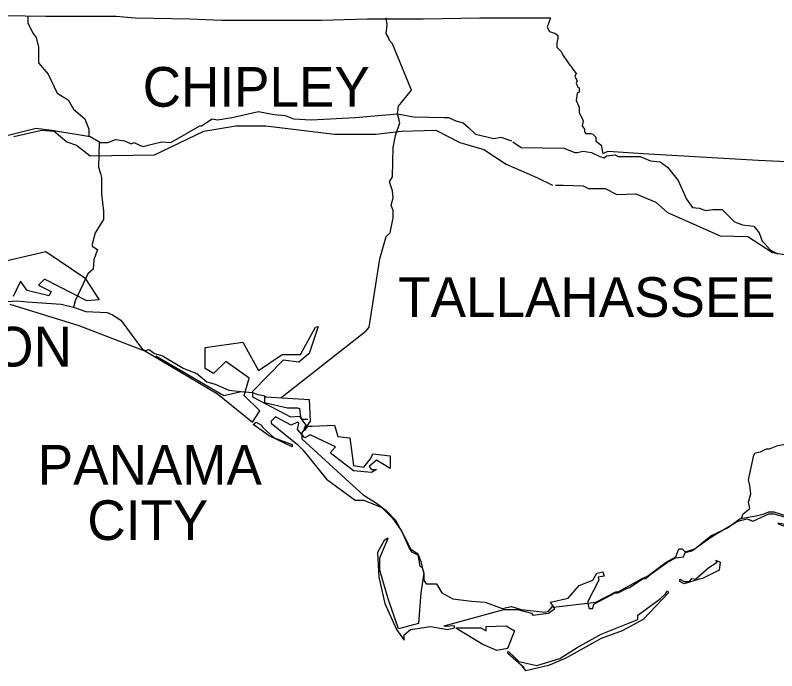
# Model space of a CAD drawing. Extents: x -820.2 to -798.1, y -2199.1 to -2182.2.
# Drawn here: x -807.968 to -807.105, y -2183.81 to -2183.067 of the extents above; entities that cross this region are included whole.
import ezdxf

# ---------------------------------------------------------------- set-up
doc = ezdxf.new("R2010")
doc.units = 0
for name, color, linetype in [('FLMap2', 7, 'Continuous'), ('FLMap3', 7, 'Continuous'), ('TextMisc', 7, 'Continuous')]:
    doc.layers.add(name, color=color, linetype=linetype)

msp = doc.modelspace()

# ---------------------------------------------------------------- linework, layer by layer
at = {"layer": 'FLMap2'}
for points in [[(-807.95384, -2183.06771), (-807.95384, -2183.07565), (-807.94789, -2183.08756), (-807.94441, -2183.09202), (-807.94193, -2183.10294), (-807.94193, -2183.1208), (-807.93102, -2183.1337), (-807.9206, -2183.15503), (-807.9082, -2183.16247), (-807.90224, -2183.17339), (-807.88934, -2183.1843), (-807.88488, -2183.19571), (-807.88488, -2183.20415)], [(-807.66708, -2183.50033), (-807.57033, -2183.42443), (-807.56686, -2183.42046), (-807.55495, -2183.34306), (-807.54751, -2183.31776), (-807.54305, -2183.3133), (-807.53957, -2183.29643), (-807.53957, -2183.28799), (-807.54206, -2183.28204), (-807.53957, -2183.27361), (-807.54057, -2183.26567), (-807.54404, -2183.25574), (-807.54057, -2183.24979), (-807.53957, -2183.21655), (-807.53709, -2183.20316), (-807.53213, -2183.18877), (-807.53461, -2183.17835), (-807.53362, -2183.16992), (-807.51874, -2183.15156), (-807.54057, -2183.09897), (-807.54404, -2183.0955), (-807.54553, -2183.09103), (-807.54751, -2183.08756), (-807.54652, -2183.07764), (-807.54751, -2183.0697)], [(-807.97765, -2183.20316), (-807.94441, -2183.19472), (-807.92655, -2183.1972), (-807.88339, -2183.20415), (-807.87148, -2183.21109), (-807.86305, -2183.21109), (-807.85461, -2183.20762), (-807.8442, -2183.20911), (-807.83675, -2183.21258), (-807.83328, -2183.21109), (-807.82733, -2183.21407), (-807.82286, -2183.21556), (-807.8174, -2183.21407), (-807.81145, -2183.21258), (-807.80202, -2183.2101), (-807.79161, -2183.21109), (-807.75886, -2183.19224), (-807.75688, -2183.19224), (-807.74497, -2183.1843), (-807.73902, -2183.1853), (-807.72215, -2183.18281), (-807.70429, -2183.17835), (-807.69238, -2183.17587), (-807.67452, -2183.17934), (-807.66212, -2183.18033), (-807.65269, -2183.1843), (-807.63285, -2183.1853), (-807.58274, -2183.18281), (-807.53461, -2183.17835), (-807.51675, -2183.18182), (-807.48202, -2183.18281), (-807.47706, -2183.18281), (-807.46863, -2183.18629), (-807.46019, -2183.18877), (-807.45474, -2183.19373), (-807.4463, -2183.20167), (-807.42547, -2183.20663), (-807.41753, -2183.20514), (-807.40562, -2183.20911)], [(-807.87297, -2183.21109), (-807.87396, -2183.23888), (-807.87148, -2183.24632), (-807.87049, -2183.25078), (-807.87049, -2183.26914), (-807.86801, -2183.28899), (-807.86801, -2183.29841), (-807.87744, -2183.3133), (-807.88091, -2183.32619), (-807.88091, -2183.32868), (-807.87495, -2183.33215), (-807.87892, -2183.34405), (-807.87992, -2183.35447), (-807.88587, -2183.35993), (-807.90026, -2183.39069), (-807.90224, -2183.39764)], [(-807.40413, -2183.2101), (-807.39471, -2183.21655), (-807.34609, -2183.21754), (-807.33368, -2183.2225), (-807.3312, -2183.2225), (-807.32426, -2183.22102), (-807.31483, -2183.2225), (-807.3054, -2183.22697), (-807.30044, -2183.22846), (-807.29796, -2183.22598), (-807.28804, -2183.22499), (-807.28457, -2183.22697), (-807.27266, -2183.22697), (-807.25976, -2183.22697), (-807.24785, -2183.23193), (-807.23694, -2183.23292), (-807.2285, -2183.23888), (-807.2166, -2183.25426), (-807.20717, -2183.27509), (-807.20023, -2183.28452), (-807.19278, -2183.28551), (-807.18534, -2183.28799), (-807.1774, -2183.287), (-807.16649, -2183.287), (-807.1526, -2183.30089), (-807.14367, -2183.30437), (-807.13077, -2183.30585), (-807.12481, -2183.3133), (-807.12134, -2183.32272), (-807.11787, -2183.32619), (-807.11192, -2183.33314), (-807.10348, -2183.33711)], [(-808.0104, -2183.35249), (-807.9335, -2183.33463), (-807.88934, -2183.3644), (-807.87297, -2183.3892), (-807.88686, -2183.39069), (-807.93499, -2183.36588), (-807.94193, -2183.37283), (-807.92754, -2183.37978), (-807.93002, -2183.38474), (-807.95483, -2183.37878), (-807.96227, -2183.36837), (-807.97071, -2183.38573)], [(-807.98261, -2183.39168), (-807.96624, -2183.39069), (-807.95483, -2183.39168), (-807.91613, -2183.39416), (-807.90224, -2183.39764), (-807.88835, -2183.4026), (-807.86404, -2183.40359), (-807.85809, -2183.40657), (-807.84866, -2183.41252), (-807.82385, -2183.44576), (-807.82038, -2183.44675), (-807.81641, -2183.44576), (-807.81046, -2183.45023), (-807.80103, -2183.45271), (-807.79954, -2183.45419), (-807.77722, -2183.46709), (-807.76233, -2183.47305), (-807.75092, -2183.48247), (-807.7415, -2183.48495), (-807.72612, -2183.4919), (-807.71223, -2183.49339), (-807.69933, -2183.49438), (-807.69337, -2183.49686), (-807.68643, -2183.49785), (-807.68395, -2183.49934), (-807.63483, -2183.50232), (-807.63384, -2183.52712), (-807.64326, -2183.54002), (-807.64326, -2183.54697), (-807.58968, -2183.59609)], [(-807.97418, -2183.39416), (-807.89629, -2183.41847)], [(-807.89629, -2183.41847), (-807.82038, -2183.44774), (-807.73902, -2183.49587), (-807.69933, -2183.52812), (-807.69089, -2183.51522), (-807.70875, -2183.49785), (-807.7028, -2183.47801), (-807.72959, -2183.45916), (-807.74348, -2183.47305), (-807.75291, -2183.46709), (-807.75291, -2183.44328), (-807.71024, -2183.43733), (-807.69238, -2183.46957), (-807.66559, -2183.45122), (-807.64475, -2183.45122), (-807.62788, -2183.42046), (-807.62491, -2183.41947), (-807.63483, -2183.45023), (-807.64674, -2183.46015), (-807.6646, -2183.45767), (-807.69933, -2183.49339), (-807.69933, -2183.49934), (-807.65616, -2183.52216)], [(-807.80897, -2183.45271), (-807.73157, -2183.49785), (-807.71223, -2183.49339)], [(-807.68544, -2183.49934), (-807.68544, -2183.50579), (-807.65964, -2183.51175), (-807.64823, -2183.51175), (-807.64575, -2183.51274), (-807.64475, -2183.52216), (-807.64326, -2183.52464), (-807.63632, -2183.52464)], [(-807.60606, -2183.53159), (-807.60258, -2183.54449), (-807.58869, -2183.54598), (-807.58472, -2183.57723), (-807.57281, -2183.57922), (-807.56537, -2183.56979), (-807.56289, -2183.56384), (-807.54305, -2183.56632), (-807.54305, -2183.58071), (-807.55843, -2183.57128), (-807.56686, -2183.57823), (-807.56438, -2183.5817), (-807.55843, -2183.5817), (-807.56438, -2183.58517), (-807.58472, -2183.58319), (-807.61102, -2183.56285), (-807.60506, -2183.5559), (-807.63384, -2183.5425), (-807.63979, -2183.54598), (-807.64823, -2183.53655), (-807.64674, -2183.52911), (-807.64823, -2183.52812), (-807.65517, -2183.53159), (-807.67303, -2183.52216), (-807.67799, -2183.52712), (-807.67799, -2183.52911), (-807.64823, -2183.55342), (-807.64227, -2183.55937), (-807.61548, -2183.59261), (-807.58274, -2183.61643), (-807.57281, -2183.61643), (-807.55247, -2183.62486), (-807.54057, -2183.63677)], [(-807.65616, -2183.52216), (-807.64575, -2183.52117), (-807.64227, -2183.52712), (-807.6388, -2183.53159), (-807.64078, -2183.53506), (-807.64078, -2183.53655), (-807.63979, -2183.53754), (-807.63632, -2183.53258), (-807.63136, -2183.53258)], [(-807.69833, -2183.5306), (-807.69486, -2183.52812), (-807.68891, -2183.53159), (-807.68742, -2183.53407)], [(-807.68742, -2183.53407), (-807.67452, -2183.54598), (-807.65418, -2183.55342), (-807.65418, -2183.5559), (-807.65418, -2183.5559), (-807.68047, -2183.5435), (-807.69833, -2183.5306)], [(-807.63136, -2183.53258), (-807.60606, -2183.53159)], [(-807.14466, -2183.63677), (-807.14268, -2183.63181), (-807.13523, -2183.62585), (-807.13672, -2183.61891), (-807.13424, -2183.60948), (-807.13523, -2183.60006), (-807.13672, -2183.59361), (-807.13077, -2183.56533), (-807.12928, -2183.56285), (-807.12333, -2183.56185), (-807.11638, -2183.55838), (-807.11291, -2183.55838), (-807.10348, -2183.55441), (-807.09703, -2183.55342), (-807.09356, -2183.55441), (-807.08512, -2183.55094)], [(-807.58968, -2183.59609), (-807.57381, -2183.61047), (-807.55843, -2183.6199), (-807.54751, -2183.62833), (-807.53709, -2183.63925), (-807.52469, -2183.66207), (-807.52023, -2183.6715), (-807.51179, -2183.67745), (-807.50832, -2183.68588), (-807.50485, -2183.70027), (-807.50485, -2183.70722), (-807.50237, -2183.71119), (-807.49046, -2183.71119), (-807.4845, -2183.72161), (-807.4721, -2183.72855), (-807.45077, -2183.73103), (-807.43539, -2183.73202), (-807.41604, -2183.73947), (-807.40562, -2183.73699), (-807.39471, -2183.74046), (-807.36742, -2183.74344), (-807.36345, -2183.74244), (-807.35899, -2183.73699), (-807.35799, -2183.73798), (-807.30987, -2183.73202), (-807.30987, -2183.73202), (-807.28705, -2183.72061), (-807.28457, -2183.72061), (-807.25728, -2183.70523), (-807.25133, -2183.70275), (-807.22999, -2183.68688), (-807.21908, -2183.68092), (-807.21561, -2183.6715), (-807.21213, -2183.6715), (-807.20866, -2183.67497), (-807.19774, -2183.6715), (-807.17939, -2183.65711), (-807.16054, -2183.64768), (-807.14664, -2183.63776), (-807.14367, -2183.63677), (-807.12829, -2183.63429), (-807.11886, -2183.63181), (-807.1139, -2183.62982), (-807.10795, -2183.62982), (-807.09356, -2183.63429)], [(-807.13871, -2183.63776), (-807.13176, -2183.64024), (-807.13176, -2183.64024), (-807.1139, -2183.63181), (-807.10795, -2183.63181), (-807.07818, -2183.64024), (-807.07669, -2183.63925), (-807.07123, -2183.6457), (-807.0757, -2183.64768), (-807.10348, -2183.64272), (-807.10249, -2183.64371), (-807.07917, -2183.65116)], [(-807.54057, -2183.63677), (-807.53015, -2183.65116), (-807.52122, -2183.6715), (-807.51874, -2183.67497), (-807.51179, -2183.67844), (-807.50931, -2183.69134), (-807.50683, -2183.69283), (-807.50485, -2183.69928), (-807.50832, -2183.72161), (-807.5108, -2183.75633), (-807.53362, -2183.76229), (-807.54553, -2183.72855), (-807.55495, -2183.69581), (-807.55495, -2183.68192), (-807.54553, -2183.65959), (-807.54999, -2183.66207), (-807.55744, -2183.67596), (-807.55595, -2183.70375), (-807.549, -2183.73351), (-807.5361, -2183.76328), (-807.52717, -2183.77519), (-807.52717, -2183.77072), (-807.52717, -2183.76923), (-807.52023, -2183.76328), (-807.4974, -2183.75981), (-807.47806, -2183.76328), (-807.47012, -2183.7613), (-807.47012, -2183.75882), (-807.48054, -2183.75981), (-807.48202, -2183.75882), (-807.41406, -2183.74046), (-807.39868, -2183.74046), (-807.3828, -2183.74443), (-807.38131, -2183.74691), (-807.36345, -2183.74443), (-807.3565, -2183.73947), (-807.36147, -2183.73202), (-807.34112, -2183.72756), (-807.32872, -2183.71317), (-807.31334, -2183.70722), (-807.30888, -2183.69928), (-807.30193, -2183.69779), (-807.30044, -2183.70275), (-807.30739, -2183.70375), (-807.3064, -2183.70722), (-807.3193, -2183.73202), (-807.31731, -2183.73947), (-807.31334, -2183.73947), (-807.31235, -2183.7345), (-807.28804, -2183.72161)], [(-807.18088, -2183.65959), (-807.17393, -2183.65513), (-807.1526, -2183.64272), (-807.14863, -2183.64024), (-807.13871, -2183.63776), (-807.13424, -2183.63925)], [(-807.28804, -2183.72161), (-807.28457, -2183.72161), (-807.27514, -2183.71664), (-807.27167, -2183.71565), (-807.25629, -2183.70523), (-807.25281, -2183.70523), (-807.24587, -2183.69928), (-807.2285, -2183.68688), (-807.21908, -2183.68192), (-807.21064, -2183.68092), (-807.20866, -2183.67596), (-807.20122, -2183.67398), (-807.18088, -2183.65959)], [(-807.21461, -2183.70871), (-807.21461, -2183.70623), (-807.20965, -2183.70871), (-807.2037, -2183.70871), (-807.20122, -2183.70523), (-807.19675, -2183.70623), (-807.18187, -2183.69283), (-807.17244, -2183.68688), (-807.17393, -2183.6844), (-807.16897, -2183.68688), (-807.16996, -2183.69581)], [(-807.16996, -2183.69581), (-807.18881, -2183.70523), (-807.19278, -2183.70623), (-807.20965, -2183.71119), (-807.21461, -2183.70871)], [(-807.39123, -2183.80644), (-807.41009, -2183.79007), (-807.40909, -2183.78809), (-807.40215, -2183.79454), (-807.39719, -2183.7995), (-807.37685, -2183.80396), (-807.35055, -2183.79602), (-807.3312, -2183.78362), (-807.30392, -2183.76824), (-807.26224, -2183.75187), (-807.26224, -2183.74691), (-807.23694, -2183.72855), (-807.23099, -2183.7226), (-807.2285, -2183.71913), (-807.22751, -2183.72161), (-807.25629, -2183.75187), (-807.2801, -2183.76477), (-807.30392, -2183.7732), (-807.3446, -2183.79602), (-807.36345, -2183.80396), (-807.38925, -2183.80992), (-807.39371, -2183.80396)], [(-807.46863, -2183.7613), (-807.44035, -2183.7613), (-807.4344, -2183.76477), (-807.4344, -2183.75981), (-807.41157, -2183.75882), (-807.40215, -2183.76477), (-807.41009, -2183.78461), (-807.42199, -2183.78709), (-807.43787, -2183.78015), (-807.46764, -2183.76229)], [(-807.46764, -2183.76229), (-807.46863, -2183.7613)]]:
    msp.add_lwpolyline(points, dxfattribs=at)
at = {"layer": 'FLMap3'}
for points in [[(-808.00395, -2183.06672), (-807.9335, -2183.06771), (-807.85362, -2183.06771), (-807.83229, -2183.0697), (-807.77027, -2183.07069), (-807.73406, -2183.07218), (-807.68544, -2183.07218), (-807.62144, -2183.07218), (-807.56885, -2183.07069), (-807.50584, -2183.07069), (-807.44134, -2183.0697), (-807.36147, -2183.0697), (-807.36494, -2183.08012), (-807.36246, -2183.08508), (-807.35551, -2183.08756), (-807.35303, -2183.08954), (-807.35303, -2183.09302), (-807.35402, -2183.09798), (-807.35402, -2183.10294), (-807.34956, -2183.1074), (-807.34708, -2183.11236), (-807.34261, -2183.11832), (-807.34112, -2183.1208), (-807.33219, -2183.13271), (-807.33368, -2183.13618), (-807.3312, -2183.14114), (-807.33219, -2183.14362), (-807.33021, -2183.14809), (-807.32872, -2183.14908), (-807.32872, -2183.15404), (-807.3312, -2183.15503), (-807.33219, -2183.16347), (-807.32872, -2183.17091), (-807.32872, -2183.17686), (-807.32426, -2183.18629), (-807.32525, -2183.19224), (-807.32277, -2183.19571), (-807.32277, -2183.19819), (-807.32178, -2183.20068), (-807.31582, -2183.20068), (-807.31334, -2183.20167), (-807.30987, -2183.20514), (-807.30987, -2183.20911), (-807.30392, -2183.21407), (-807.30193, -2183.2235), (-807.29598, -2183.22102), (-807.25629, -2183.2235), (-807.19774, -2183.22697), (-807.12581, -2183.23094), (-807.05337, -2183.23441)], [(-807.96971, -2183.20415), (-807.93846, -2183.1972), (-807.92407, -2183.19819), (-807.90968, -2183.2101), (-807.89877, -2183.21407), (-807.88339, -2183.22598), (-807.81046, -2183.22499), (-807.7544, -2183.19819), (-807.71818, -2183.19224), (-807.68395, -2183.19224), (-807.60606, -2183.20167), (-807.55942, -2183.20167), (-807.53015, -2183.19819), (-807.49145, -2183.1972), (-807.46416, -2183.21109), (-807.43688, -2183.21903), (-807.41157, -2183.2354), (-807.37685, -2183.25078), (-807.35899, -2183.25922)], [(-807.35551, -2183.25922), (-807.34708, -2183.25922), (-807.32426, -2183.26021), (-807.3183, -2183.26319), (-807.29945, -2183.26319), (-807.28606, -2183.27013), (-807.26472, -2183.26914), (-807.2419, -2183.27857), (-807.2285, -2183.29047), (-807.16897, -2183.31677), (-807.13771, -2183.31776), (-807.10943, -2183.33562), (-807.06032, -2183.34405)]]:
    msp.add_lwpolyline(points, dxfattribs=at)

# ---------------------------------------------------------------- texts
at = {"layer": 'TextMisc'}
for s, p in [('CHIPLEY', (-807.82368, -2183.17045)), ('TALLAHASSEE', (-807.53402, -2183.40878)), ('FORT WALTON', (-808.34197, -2183.46497)), ('PANAMA', (-807.94269, -2183.59895)), ('CITY', (-807.88647, -2183.66166))]:
    msp.add_text(s, height=0.045, dxfattribs=at).set_placement(p)

doc.saveas('drawing.dxf')
